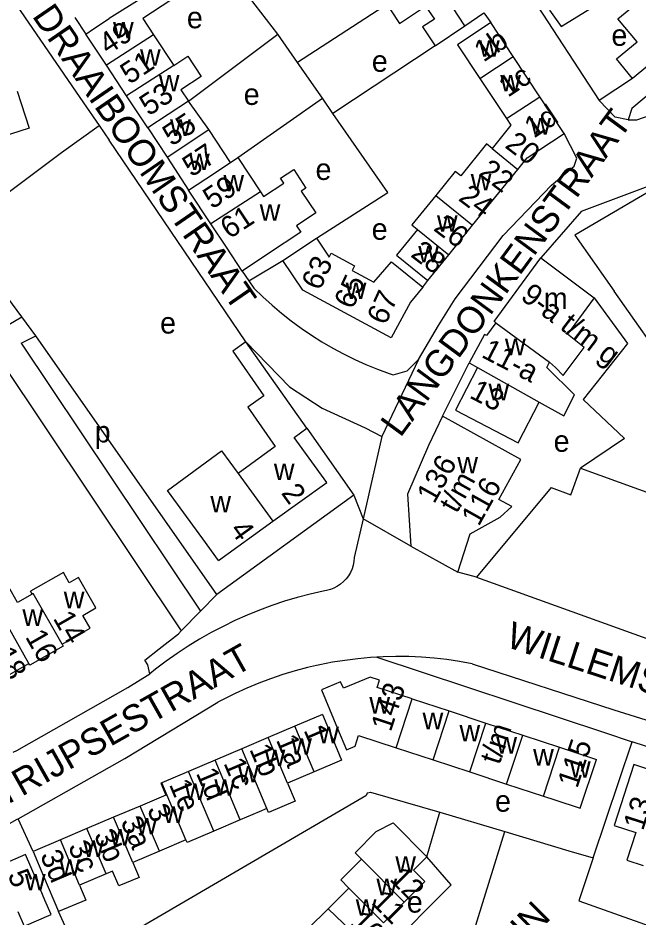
# Model space of a CAD drawing. Extents: x 159261 to 160849, y 382514 to 384534.
# Drawn here: x 160238.9 to 160354.6, y 383295.6 to 383463.4 of the extents above; entities that cross this region are included whole.
import ezdxf

# ---------------------------------------------------------------- set-up
doc = ezdxf.new("R2010")
doc.units = 0
for name, color, linetype in [('BLT_Basislijn', 7, 'Continuous'), ('BLT_Bebouwing', 7, 'Continuous'), ('BLT_Centroide', 7, 'Continuous'), ('BLT_Huisnummer', 7, 'Continuous'), ('BLT_Huisnummer_ tussenligend', 7, 'Continuous'), ('BLT_Huisnummer_reeks', 7, 'Continuous'), ('BLT_Onderverdeling_panden', 7, 'Continuous'), ('BLT_Straatnaam', 7, 'Continuous'), ('BLT_Vlakafsluiter', 7, 'Continuous')]:
    doc.layers.add(name, color=color, linetype=linetype)

msp = doc.modelspace()

# ---------------------------------------------------------------- linework, layer by layer
at = {"layer": 'BLT_Basislijn'}
for p, q in [((160287.38, 383460.38), (160275.29, 383475.98)), ((160334.4, 383467.92), (160347.36, 383447.97)), ((160308.24, 383466.2), (160291.06, 383455.07)), ((160249.49, 383463.44), (160251.5, 383460.38)), ((160322.29, 383461.92), (160325.85, 383464.35)), ((160325.85, 383464.35), (160327.16, 383462.51)), ((160270.7, 383447.84), (160287.38, 383460.38)), ((160291.06, 383455.07), (160287.38, 383460.38)), ((160316.73, 383458.2), (160297.65, 383445.58)), ((160295.69, 383448.41), (160291.06, 383455.07)), ((160353.57, 383452.09), (160347.36, 383447.97)), ((160279.9, 383437.35), (160295.69, 383448.41)), ((160297.65, 383445.58), (160295.69, 383448.41)), ((160251.11, 383447.53), (160253.99, 383443.3)), ((160307.91, 383430.81), (160297.65, 383445.58)), ((160246.96, 383438.28), (160253.99, 383443.3)), ((160253.99, 383443.3), (160255.86, 383440.57)), ((160281.42, 383402.93), (160255.86, 383440.57)), ((160227.67, 383423.78), (160246.96, 383438.28)), ((160344.05, 383427.35), (160361.94, 383434.03)), ((160294.57, 383422.3), (160307.91, 383430.81)), ((160344.05, 383427.35), (160336.49, 383418.61)), ((160239.57, 383407.59), (160227.67, 383423.78)), ((160281.95, 383414.35), (160288.33, 383418.11)), ((160280.73, 383416.16), (160281.95, 383414.35)), ((160281.95, 383414.35), (160282.91, 383412.93)), ((160314.43, 383413.14), (160315.4, 383414.38)), ((160210.53, 383390.65), (160239.57, 383407.59)), ((160242.17, 383404.07), (160239.57, 383407.59)), ((160239.47, 383402.67), (160242.17, 383404.07)), ((160276, 383355.82), (160242.17, 383404.07)), ((160239.47, 383402.67), (160272.91, 383352.67)), ((160235.59, 383399.48), (160269.33, 383349.02)), ((160313.62, 383399.64), (160306.79, 383385.3)), ((160318.11, 383389.07), (160323.06, 383399.01)), ((160292.76, 383386.82), (160301.56, 383374.34)), ((160306.79, 383385.3), (160303.3, 383369.95)), ((160301.56, 383374.34), (160276, 383355.82)), ((160301.56, 383374.34), (160303.3, 383369.95)), ((160303.3, 383369.95), (160301.65, 383362.71)), ((160324.44, 383359.03), (160320.96, 383359.97)), ((160276, 383355.82), (160272.91, 383352.67)), ((160272.91, 383352.67), (160269.33, 383349.02)), ((160265.21, 383345.68), (160268.8, 383348.48)), ((160269.33, 383349.02), (160268.8, 383348.48)), ((160262.53, 383343.57), (160265.21, 383345.68)), ((160305.85, 383344.11), (160348.33, 383330.08)), ((160258.82, 383325.22), (160276.16, 383335.7)), ((160348.33, 383330.08), (160353.53, 383328.34)), ((160346.22, 383306.67), (160353.53, 383328.34)), ((160238.87, 383313.98), (160258.82, 383325.22)), ((160315.19, 383306.89), (160317.62, 383315.21)), ((160317.62, 383315.21), (160329.78, 383311.57)), ((160241.67, 383307.85), (160238.87, 383313.98)), ((160324.02, 383293.13), (160329.78, 383311.57)), ((160319.7, 383301.63), (160315.19, 383306.89)), ((160249.76, 383289.39), (160246.43, 383296.64))]:
    msp.add_line(p, q, dxfattribs=at)
for points in [[(160183.02, 383462.34), (160192.01, 383464.26), (160233.34, 383472.32), (160234.15, 383472.15), (160251.11, 383447.53)], [(160365.66, 383448.28), (160361.65, 383452.87), (160361.1, 383452.91), (160353.47, 383446.51), (160352.76, 383444.37)], [(160352.76, 383444.37), (160350.34, 383444.89), (160347.36, 383447.97)], [(160352.76, 383444.37), (160354.41, 383444.35), (160365.66, 383448.28)], [(160313.62, 383399.64), (160317.37, 383405.99), (160320.49, 383411), (160329.42, 383422.76), (160338.49, 383432.18), (160342.69, 383435.72), (160343.17, 383437.22), (160340.82, 383441.83)], [(160282.91, 383412.93), (160284.57, 383411.32), (160286.29, 383409.77), (160288.05, 383408.28), (160289.87, 383406.85), (160291.74, 383405.48), (160293.65, 383404.18), (160295.61, 383402.94), (160297.61, 383401.78), (160299.64, 383400.68), (160301.72, 383399.65), (160303.83, 383398.7), (160305.97, 383397.82), (160308.14, 383397.02), (160308.89, 383396.76)], [(160346.42, 383411.14), (160352.64, 383402.66), (160344.39, 383392.21), (160352.07, 383384.93), (160343.86, 383379.35)], [(160281.42, 383402.93), (160289.55, 383394.55), (160295.67, 383390.58), (160303.66, 383386.91), (160306.79, 383385.3)], [(160308.89, 383396.76), (160311.5, 383397.54), (160313.62, 383399.64)], [(160301.65, 383362.71), (160301.59, 383361.99), (160301.45, 383361.28), (160301.22, 383360.59), (160300.93, 383359.93), (160300.56, 383359.31), (160300.13, 383358.74), (160299.64, 383358.21), (160299.09, 383357.74), (160298.49, 383357.33), (160297.85, 383357), (160297.18, 383356.73), (160296.48, 383356.55), (160295.84, 383356.44)], [(160295.84, 383356.44), (160293.41, 383355.89), (160291.01, 383355.25), (160288.63, 383354.54), (160286.27, 383353.75), (160283.94, 383352.89), (160281.64, 383351.95), (160279.37, 383350.94), (160277.14, 383349.86), (160274.93, 383348.7), (160272.77, 383347.47), (160270.65, 383346.18), (160268.57, 383344.82), (160266.54, 383343.39), (160264.55, 383341.9), (160263.46, 383341.03)], [(160263.46, 383341.03), (160263.11, 383342.68), (160262.53, 383343.57)], [(160305.85, 383344.11), (160304.65, 383344.04), (160302.28, 383343.82), (160299.91, 383343.52), (160297.55, 383343.15), (160295.21, 383342.69), (160294.56, 383342.54)], [(160323.65, 383342.9), (160321.3, 383343.32), (160318.94, 383343.66), (160316.57, 383343.92), (160314.19, 383344.11), (160311.81, 383344.21), (160309.42, 383344.23), (160307.04, 383344.17), (160305.85, 383344.11)], [(160323.65, 383342.9), (160350.12, 383334.27), (160373.6, 383326.96), (160385.68, 383323.64), (160401.99, 383321), (160424.84, 383318.1)], [(160237.95, 383326.36), (160238.62, 383326.71), (160259.39, 383338.47), (160263.46, 383341.03)], [(160294.56, 383342.54), (160292.88, 383342.16), (160290.58, 383341.55), (160288.29, 383340.86), (160286.03, 383340.1), (160283.8, 383339.26), (160281.59, 383338.34), (160279.42, 383337.36), (160277.28, 383336.3), (160276.16, 383335.7)], [(160397.45, 383314.44), (160376.9, 383320.73), (160353.53, 383328.34)], [(160304.12, 383318.81), (160303.77, 383318.26), (160253.18, 383288.68)], [(160304.12, 383318.81), (160304.66, 383318.95), (160317.62, 383315.21)], [(160181.62, 383289.04), (160231.89, 383310.05), (160238.71, 383313.89), (160238.87, 383313.98)], [(160329.78, 383311.57), (160341.7, 383308), (160346.22, 383306.67)], [(160346.22, 383306.67), (160343.57, 383298.62), (160357.75, 383293.62), (160358.12, 383293.16), (160345.81, 383255.92), (160343.79, 383253.59), (160299.81, 383210.07), (160298.37, 383208.54), (160297.67, 383207.17), (160307.76, 383196.76), (160312.17, 383192.63), (160320.09, 383186.16), (160328.46, 383180.84), (160334.97, 383177.44), (160342.22, 383174.09), (160343.74, 383173.64), (160347.8, 383173.48)], [(160303.4, 383290.85), (160307.35, 383289.19), (160319.7, 383301.63)]]:
    msp.add_lwpolyline(points, dxfattribs=at)
at = {"layer": 'BLT_Bebouwing'}
for p, q in [((160265.81, 383469.5), (160255.91, 383463.3)), ((160252.93, 383461.33), (160255.91, 383463.3)), ((160316.73, 383458.2), (160322.29, 383461.92)), ((160331.32, 383456.2), (160327.16, 383462.51)), ((160362.31, 383459.29), (160353.57, 383452.09)), ((160336.3, 383448.67), (160331.32, 383456.2)), ((160259.14, 383448.86), (160255.36, 383454.54)), ((160325.09, 383452.05), (160330.04, 383444.59)), ((160263.11, 383442.88), (160259.14, 383448.86)), ((160340.82, 383441.83), (160336.3, 383448.67)), ((160274.5, 383442.54), (160270.7, 383447.84)), ((160263.11, 383442.88), (160266.71, 383437.4)), ((160278.51, 383436.43), (160274.5, 383442.54)), ((160266.71, 383437.4), (160270.72, 383431.27)), ((160278.51, 383436.43), (160279.9, 383437.35)), ((160279.9, 383437.35), (160284.15, 383430.92)), ((160323.74, 383424.7), (160332.17, 383435.13)), ((160274.89, 383424.98), (160270.72, 383431.27)), ((160277.79, 383420.59), (160274.89, 383424.98)), ((160291.65, 383423.39), (160285.63, 383419.41)), ((160319.28, 383419.17), (160323.74, 383424.7)), ((160288.33, 383418.11), (160294.57, 383422.3)), ((160280.73, 383416.16), (160277.79, 383420.59)), ((160285.63, 383419.41), (160280.73, 383416.16)), ((160315.4, 383414.38), (160319.28, 383419.17)), ((160327.76, 383406.72), (160336.49, 383418.61)), ((160346.42, 383411.14), (160341.43, 383404.38)), ((160344.59, 383401.91), (160341.43, 383404.38)), ((160292.76, 383386.82), (160281.42, 383402.93)), ((160324.67, 383398.17), (160320.53, 383390.2)), ((160320.53, 383390.2), (160332.25, 383384.12)), ((160276.27, 383362.12), (160286.43, 383369.46)), ((160312.19, 383364.82), (160320.96, 383359.97)), ((160324.44, 383359.03), (160372.32, 383341.84)), ((160241.52, 383355.86), (160241.19, 383356.43)), ((160312.46, 383336.34), (160319.34, 383334.08)), ((160295.68, 383333.39), (160290.56, 383331.22)), ((160319.34, 383334.08), (160326.21, 383331.82)), ((160290.56, 383331.22), (160285.59, 383329.11)), ((160326.21, 383331.82), (160333.09, 383329.57)), ((160333.09, 383329.57), (160339.96, 383327.31)), ((160285.59, 383329.11), (160280.62, 383327)), ((160280.62, 383327), (160275.65, 383324.89)), ((160309.46, 383327.21), (160316.34, 383324.96)), ((160339.96, 383327.31), (160346.84, 383325.05)), ((160275.65, 383324.89), (160270.68, 383322.78)), ((160316.34, 383324.96), (160323.21, 383322.7)), ((160270.68, 383322.78), (160265.71, 383320.67)), ((160294.16, 383322.73), (160289.19, 383320.62)), ((160323.21, 383322.7), (160330.09, 383320.44)), ((160330.09, 383320.44), (160336.96, 383318.18)), ((160261.68, 383316.34), (160256.71, 383314.23)), ((160256.71, 383314.23), (160251.73, 383312.12)), ((160251.73, 383312.12), (160246.77, 383310.01)), ((160246.77, 383310.01), (160241.67, 383307.85)), ((160265.25, 383307.92), (160260.28, 383305.81)), ((160255.31, 383303.7), (160250.34, 383301.59)), ((160296.74, 383297.18), (160300.6, 383301.04)), ((160310.96, 383298.39), (160307.09, 383294.54)), ((160293.01, 383293.46), (160296.74, 383297.18))]:
    msp.add_line(p, q, dxfattribs=at)
for points in [[(160320.33, 383472.82), (160316.16, 383470.07), (160308.39, 383464.92), (160310.11, 383462.34), (160314.97, 383465.59), (160316.6, 383463.17), (160314.39, 383461.69), (160316.73, 383458.2)], [(160265.81, 383469.5), (160267.56, 383466.86), (160262.15, 383463.27), (160264.17, 383460.23)], [(160338.07, 383464.84), (160340.24, 383461.78), (160346.44, 383465.55), (160344.49, 383468.79)], [(160322.29, 383461.92), (160320.06, 383465.35), (160323.68, 383467.76)], [(160353.57, 383452.09), (160350.59, 383455.72), (160354.44, 383458.89), (160350.87, 383463.2), (160354.56, 383466.25)], [(160327.16, 383462.51), (160320.91, 383458.36), (160325.09, 383452.05)], [(160251.5, 383460.38), (160252.93, 383461.33)], [(160255.36, 383454.54), (160251.5, 383460.38)], [(160264.17, 383460.23), (160267.95, 383454.52)], [(160267.95, 383454.52), (160270.6, 383456.22), (160273.08, 383452.48), (160269.29, 383449.97), (160270.7, 383447.84)], [(160238.71, 383449.73), (160240.92, 383442.82), (160228.52, 383438.86)], [(160330.04, 383444.59), (160330.85, 383443.36), (160327.36, 383439.01)], [(160332.17, 383435.13), (160333.9, 383437.27), (160340.82, 383441.83)], [(160327.36, 383439.01), (160326.32, 383439.86), (160321.51, 383433.9), (160320.45, 383434.75), (160316.84, 383430.28)], [(160287.86, 383433.48), (160290.33, 383435.11), (160292.63, 383431.63), (160291.75, 383431.05), (160294.44, 383426.99), (160290.85, 383424.61), (160291.65, 383423.39)], [(160284.15, 383430.92), (160284.71, 383430.08), (160288.47, 383432.57), (160287.86, 383433.48)], [(160361.94, 383434.03), (160342.8, 383422.87), (160350.18, 383412.42)], [(160316.84, 383430.28), (160312.38, 383424.75), (160313.43, 383423.9)], [(160313.43, 383423.9), (160309.55, 383419.1), (160315.4, 383414.38)], [(160294.57, 383422.3), (160296.96, 383418.73), (160297.35, 383419.46), (160301.7, 383417.11), (160301.23, 383416.23), (160305.28, 383414.05), (160308.57, 383417.88), (160314.43, 383413.14)], [(160336.49, 383418.61), (160340.45, 383415.65), (160346.42, 383411.14)], [(160314.43, 383413.14), (160312.11, 383410.33), (160308.54, 383403.7), (160292.03, 383412.59), (160288.33, 383418.11)], [(160343.86, 383379.35), (160383.59, 383365.03), (160350.18, 383412.42)], [(160328.07, 383406.49), (160326.35, 383404.11), (160325.93, 383404.33), (160323.06, 383399.01)], [(160328.07, 383406.49), (160327.76, 383406.72)], [(160281.42, 383402.93), (160278.99, 383401.23), (160284.78, 383392.85), (160281.76, 383390.73), (160286.9, 383383.41), (160279.97, 383378.4)], [(160338.1, 383399.14), (160339.21, 383398.18), (160340.63, 383396.67), (160344.59, 383401.91)], [(160323.06, 383399.01), (160324.67, 383398.17)], [(160336.18, 383391.7), (160340.74, 383389.14), (160342.78, 383393.07), (160337.6, 383398.18), (160338.1, 383399.14)], [(160332.25, 383384.12), (160336.18, 383391.7)], [(160318.11, 383389.07), (160315.48, 383383.61), (160311.55, 383374.51), (160312.19, 383364.82)], [(160331.05, 383372.22), (160328.64, 383373.55), (160332.76, 383380.99), (160318.11, 383389.07)], [(160286.43, 383369.46), (160296.5, 383376.7), (160290.41, 383385.12), (160292.76, 383386.82)], [(160266.8, 383375.21), (160276.87, 383382.61), (160279.97, 383378.4)], [(160338.38, 383375.79), (160342.09, 383374.42), (160343.86, 383379.35)], [(160276.27, 383362.12), (160273.34, 383366.17), (160266.8, 383375.21)], [(160338.38, 383375.79), (160324.44, 383359.03)], [(160320.96, 383359.97), (160323.26, 383367.11), (160328.87, 383370.21), (160331.05, 383372.22)], [(160241.52, 383355.86), (160238.76, 383354.32), (160235.35, 383360.31), (160232.22, 383358.52)], [(160247.12, 383346.53), (160252.31, 383349.5), (160250.94, 383351.9), (160253.41, 383353.31), (160250.93, 383357.65), (160250.18, 383358.97), (160248.44, 383357.98), (160247.33, 383359.94), (160241.19, 383356.43)], [(160234.87, 383353.64), (160228.88, 383350.22), (160230, 383348.24), (160228.26, 383347.23), (160229.03, 383345.85), (160231.51, 383341.51), (160233.99, 383342.93), (160235.68, 383339.96), (160240.91, 383342.94)], [(160247.12, 383346.53), (160247.32, 383346.18), (160241.09, 383342.62), (160240.91, 383342.94)], [(160312.46, 383336.34), (160305.93, 383338.48), (160306.37, 383339.8), (160304.59, 383340.38), (160299.6, 383338.3), (160299.08, 383339.51), (160295.52, 383338.01), (160298.51, 383330.81), (160300.17, 383326.82), (160301.78, 383327.49), (160302.45, 383329.52), (160309.46, 383327.21)], [(160295.68, 383333.39), (160297.63, 383328.79), (160299.28, 383324.9), (160294.16, 383322.73)], [(160336.96, 383318.18), (160339.09, 383317.48), (160343.84, 383315.92), (160346.84, 383325.05)], [(160361.01, 383321.72), (160353.85, 383324.07), (160350.13, 383312.73), (160354.22, 383311.39), (160352.53, 383306.23), (160355.6, 383305.23)], [(160265.71, 383320.67), (160265.53, 383320.6), (160266.47, 383318.38), (160261.68, 383316.34)], [(160289.19, 383320.62), (160290.63, 383317.23), (160285.65, 383315.12), (160285.34, 383315.87)], [(160285.34, 383315.87), (160283.89, 383315.25), (160280.37, 383313.76)], [(160280.37, 383313.76), (160275.43, 383311.66)], [(160302.99, 383306.41), (160301.78, 383307.6), (160305.71, 383311.57), (160308.89, 383313.2), (160315.19, 383306.89)], [(160275.43, 383311.66), (160270.43, 383309.54), (160270.22, 383310.03)], [(160270.22, 383310.03), (160265.25, 383307.92)], [(160241.67, 383307.85), (160243.63, 383303.25), (160246.43, 383296.64)], [(160238.85, 383296.66), (160239.99, 383293.92), (160245.05, 383296.07), (160243.89, 383298.8), (160242.25, 383302.68), (160240.29, 383307.28), (160235.25, 383305.14)], [(160260.28, 383305.81), (160261.49, 383303.03), (160257.71, 383301.43), (160256.52, 383304.21), (160255.31, 383303.7)], [(160300.6, 383301.04), (160299.16, 383302.56), (160302.99, 383306.41)], [(160315.19, 383306.89), (160312.68, 383304.38), (160314.81, 383302.24), (160310.96, 383298.39)], [(160250.34, 383301.59), (160251.51, 383298.8), (160246.43, 383296.64)]]:
    msp.add_lwpolyline(points, dxfattribs=at)
at = {"layer": 'BLT_Onderverdeling_panden'}
for p, q in [((160264.17, 383460.23), (160255.36, 383454.54)), ((160325.09, 383452.05), (160331.32, 383456.2)), ((160267.95, 383454.52), (160259.14, 383448.86)), ((160330.04, 383444.59), (160336.3, 383448.67)), ((160270.7, 383447.84), (160263.11, 383442.88)), ((160266.71, 383437.4), (160274.5, 383442.54)), ((160327.36, 383439.01), (160332.17, 383435.13)), ((160273.9, 383433.38), (160278.51, 383436.43)), ((160270.72, 383431.27), (160273.9, 383433.38)), ((160284.15, 383430.92), (160274.89, 383424.98)), ((160316.84, 383430.28), (160323.74, 383424.7)), ((160313.43, 383423.9), (160319.28, 383419.17)), ((160328.07, 383406.49), (160338.1, 383399.14)), ((160324.67, 383398.17), (160336.18, 383391.7)), ((160279.97, 383378.4), (160286.43, 383369.46)), ((160240.91, 383342.94), (160234.87, 383353.64)), ((160309.46, 383327.21), (160312.46, 383336.34)), ((160316.34, 383324.96), (160319.34, 383334.08)), ((160294.16, 383322.73), (160290.56, 383331.22)), ((160323.21, 383322.7), (160326.21, 383331.82)), ((160330.09, 383320.44), (160333.09, 383329.57)), ((160289.19, 383320.62), (160285.59, 383329.11)), ((160285.34, 383315.87), (160280.62, 383327)), ((160336.96, 383318.18), (160339.96, 383327.31)), ((160280.37, 383313.76), (160275.65, 383324.89)), ((160275.43, 383311.66), (160270.68, 383322.78)), ((160270.22, 383310.03), (160265.71, 383320.67)), ((160265.25, 383307.92), (160261.68, 383316.34)), ((160260.28, 383305.81), (160256.71, 383314.23)), ((160255.31, 383303.7), (160251.73, 383312.12)), ((160250.34, 383301.59), (160246.77, 383310.01)), ((160310.96, 383298.39), (160302.99, 383306.41)), ((160307.09, 383294.54), (160300.6, 383301.04)), ((160303.4, 383290.85), (160296.74, 383297.18))]:
    msp.add_line(p, q, dxfattribs=at)
msp.add_lwpolyline([(160247.12, 383346.53), (160241.71, 383355.97), (160241.52, 383355.86)], dxfattribs=at)
at = {"layer": 'BLT_Vlakafsluiter'}
msp.add_line((160312.19, 383364.82), (160303.3, 383369.95), dxfattribs=at)

# ---------------------------------------------------------------- texts
at = {"layer": 'BLT_Centroide'}
for s, p in [('e', (160270.39, 383461.45)), ('w', (160256.6, 383459.56)), ('e', (160349.65, 383458.17)), ('w', (160324.93, 383456.13)), ('w', (160261.64, 383454.47)), ('e', (160304.92, 383453.33)), ('w', (160265.15, 383449.69)), ('w', (160328.9, 383449.68)), ('e', (160281, 383447.15)), ('w', (160267.26, 383441.36)), ('w', (160334.49, 383441.61)), ('w', (160270.8, 383435)), ('e', (160294.41, 383433.15)), ('w', (160277.21, 383431.03)), ('w', (160323.38, 383431.2)), ('w', (160283.98, 383425.53)), ('w', (160317.08, 383423.49)), ('e', (160304.89, 383421.99)), ('w', (160313.58, 383417.77)), ('w', (160300.04, 383410.94)), ('m', (160337.03, 383409.06)), ('e', (160265.39, 383404.49)), ('w', (160329.78, 383400.44)), ('w', (160326.7, 383392.06)), ('p', (160253.18, 383384.17)), ('e', (160338.86, 383382.43)), ('w', (160320.88, 383378.4)), ('w', (160286.63, 383377.17)), ('w', (160274.78, 383371.12)), ('w', (160247.41, 383353.25)), ('w', (160239.69, 383349.95)), ('w', (160304.46, 383333.59)), ('w', (160314.39, 383330.66)), ('w', (160294.92, 383328.06)), ('w', (160321.28, 383328.39)), ('w', (160289.88, 383325.92)), ('w', (160328.16, 383326.12)), ('w', (160284.91, 383323.81)), ('w', (160335.03, 383323.88)), ('w', (160341.91, 383321.61)), ('w', (160279.94, 383320.75)), ('w', (160275.52, 383318.27)), ('w', (160269.98, 383317.48)), ('e', (160327.92, 383315.28)), ('w', (160265.95, 383313.19)), ('w', (160260.97, 383311.06)), ('w', (160256, 383308.97)), ('w', (160251.03, 383306.84)), ('w', (160246.59, 383303.33)), ('w', (160309.3, 383303.91)), ('w', (160240.16, 383300.61)), ('w', (160305.78, 383299.7)), ('e', (160311.45, 383296.45)), ('w', (160301.92, 383295.86))]:
    msp.add_text(s, height=4, dxfattribs=at).set_placement(p)
at = {"layer": 'BLT_Huisnummer'}
for s, rotation, p in [('49', 33.5001, (160255.68, 383456.41)), ('1b', 33.7826, (160325.75, 383455.02)), ('1c', 33.7826, (160330.32, 383448.46)), ('53', 33.5105, (160263.26, 383444.98)), ('55', 33.5105, (160267.56, 383439.33)), ('57', 33.5105, (160271.27, 383433.57)), ('59', 33.4989, (160275.11, 383427.6)), ('61', 33.5057, (160278.34, 383422.03)), ('26', 322.9247, (160316.24, 383423.87)), ('28', 322.9247, (160311.98, 383418.98)), ('13', 332.5687, (160322.95, 383392.6)), ('2', 305.8681, (160287.88, 383374.73)), ('4', 305.8614, (160278.29, 383367.86)), ('14', 299.735, (160245.32, 383351.37)), ('18', 299.7335, (160234.31, 383344.67)), ('1', 293.0012, (160292.13, 383330.52)), ('1a', 293.0012, (160286.97, 383328.7)), ('1b', 293.0012, (160282.01, 383326.95)), ('1c', 292.9988, (160277.18, 383324.36)), ('1d', 292.9988, (160272.04, 383322.49)), ('1e', 292.9988, (160267.01, 383320.38)), ('3', 292.9971, (160262.89, 383315.72)), ('3a', 293.0029, (160257.96, 383313.45)), ('3b', 293.0029, (160252.98, 383310.97)), ('3c', 293.0004, (160248.15, 383308.82)), ('3d', 293.006, (160242.93, 383307.16)), ('5', 293, (160236.87, 383303.51)), ('12', 314.9595, (160308.04, 383302.57)), ('11', 314.9603, (160304.61, 383298.23)), ('10', 314.9595, (160300.66, 383294.39))]:
    msp.add_text(s, height=4, rotation=rotation, dxfattribs=at).set_placement(p)
at = {"layer": 'BLT_Huisnummer_ tussenligend'}
for s, rotation, p in [('51', 33.5001, (160259.67, 383450.88)), ('16', 299.7357, (160240.13, 383347.91))]:
    msp.add_text(s, height=4, rotation=rotation, dxfattribs=at).set_placement(p)
at = {"layer": 'BLT_Huisnummer_reeks'}
for s, rotation, p in [('1d', 33.7826, (160335.13, 383440.81)), ('20', 322.9247, (160329.58, 383439.31)), ('22', 322.9247, (160324.67, 383434.17)), ('24', 322.9247, (160320.89, 383429.47)), ('63', 65.5105, (160295.24, 383412.35)), ('65', 65.5105, (160301.32, 383408.84)), ('9-a t/m g', 322.9247, (160332.49, 383411.01)), ('67', 65.5105, (160307.46, 383405.89)), ('11-a', 332.5702, (160325.18, 383400.19)), ('136', 60.7388, (160316.55, 383372.57)), ('t/m', 60.7388, (160320.76, 383370.78)), ('116', 60.7388, (160324.88, 383368.38)), ('143', 71.8364, (160308.45, 383330.03)), ('t/m', 71.8317, (160328.76, 383323.89)), ('115', 71.8359, (160343.27, 383319.49)), ('13', 71.8364, (160355.54, 383311.6))]:
    msp.add_text(s, height=4, rotation=rotation, dxfattribs=at).set_placement(p)
at = {"layer": 'BLT_Straatnaam'}
for s, height, rotation, p in [('SCHOUWBROEKSEWEG', 5, 11.9132, (160167.73, 383461.79)), ('DRAAIBOOMSTRAAT', 5, 304.5268, (160241.38, 383463.73)), ('LANGDONKENSTRAAT', 5, 53.6265, (160310.25, 383384.94)), ('WILLEMSTRAAT', 5, 341.9397, (160329.73, 383346.1)), ('STRIJPSESTRAAT', 4.9999, 29.3976, (160232.13, 383313.86)), ('WOUTER HOLLEMANPLEIN', 5, 44.9045, (160276.46, 383233.52))]:
    msp.add_text(s, height=height, rotation=rotation, dxfattribs=at).set_placement(p)

doc.saveas('drawing.dxf')
